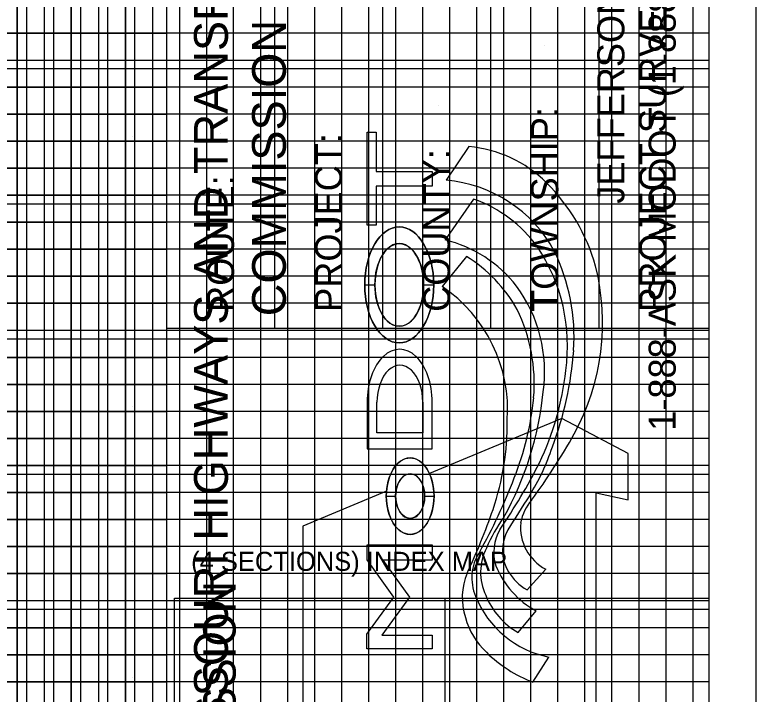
# Model space of a CAD drawing. Extents: x 90.2 to 116.7, y 59.2 to 76.5.
import ezdxf

# ---------------------------------------------------------------- set-up
doc = ezdxf.new("R2010")
doc.units = 0
for name, color, linetype in [('Border-Border', 7, 'Continuous'), ('Border-Bridge survey map and note', 7, 'Continuous'), ('Border-Cookie Cutter Template', 7, 'Continuous'), ('Border-English bridge partial major lines', 7, 'Continuous'), ('Border-English bridge partial minor lines', 7, 'Continuous'), ('Border-English bridge xsection major lines', 7, 'Continuous'), ('Border-English bridge xsection minor lines', 7, 'Continuous'), ('Border-English xsection major lines', 7, 'Continuous'), ('Border-English xsection minor lines', 7, 'Continuous'), ('Border-Full profile major grid lines', 7, 'Continuous'), ('Border-Geopak xsection major grid lines', 7, 'Continuous'), ('Border-Geopak xsection minor lines 1', 7, 'Continuous'), ('Border-Geopak xsection minor lines 2', 7, 'Continuous'), ('Border-Plan-profile major grid lines', 7, 'Continuous'), ('Border-Plotting block', 7, 'Continuous'), ('Border-Title block - A-size Landscape Electronic Seal', 7, 'Continuous'), ('Border-Title block - Final Plans Consultant Manual Seal', 7, 'Continuous'), ('Border-Title block - Final Plans Electronic Seal', 7, 'Continuous'), ('Border-Title block - Location Survey Electronic Seal', 7, 'Continuous'), ('Border-Xsection shape', 7, 'Continuous')]:
    doc.layers.add(name, color=color, linetype=linetype)

msp = doc.modelspace()

# ---------------------------------------------------------------- linework, layer by layer
at = {"layer": 'Border-Border'}
msp.add_line((116.4051, 76.3159), (116.4051, 59.3368), dxfattribs=at)
at = {"layer": 'Border-Bridge survey map and note'}
msp.add_line((115.5901, 64.3446), (115.5901, 62.6635), dxfattribs=at)
msp.add_lwpolyline([(114.7568, 62.6635), (114.7568, 64.3446), (116.4051, 64.3446)], dxfattribs=at)
at = {"layer": 'Border-Cookie Cutter Template'}
for p, q in [((114.7319, 76.3159), (114.7319, 59.3368)), ((116.4051, 76.3159), (116.4051, 59.3368))]:
    msp.add_line(p, q, dxfattribs=at)
at = {"layer": 'Border-English bridge partial major lines'}
for p, q in [((114.9385, 62.6701), (114.9385, 76.3159)), ((115.7718, 76.3159), (115.7718, 62.6701)), ((90.3636, 66.0034), (116.4051, 66.0034)), ((90.3636, 65.1701), (116.4051, 65.1701)), ((90.3636, 64.3368), (116.4051, 64.3368))]:
    msp.add_line(p, q, dxfattribs=at)
at = {"layer": 'Border-English bridge partial minor lines'}
for p, q in [((114.2718, 76.3159), (114.2718, 62.6701)), ((114.3551, 76.3159), (114.3551, 62.6701)), ((114.4385, 76.3159), (114.4385, 62.6701)), ((114.5218, 76.3159), (114.5218, 62.6701)), ((114.6051, 76.3159), (114.6051, 62.6701)), ((114.6885, 76.3159), (114.6885, 62.6701)), ((114.7718, 76.3159), (114.7718, 62.6701)), ((114.8551, 76.3159), (114.8551, 62.6701)), ((115.0218, 76.3159), (115.0218, 62.6701)), ((115.1051, 76.3159), (115.1051, 62.6701)), ((115.1885, 76.3159), (115.1885, 62.6701)), ((115.2718, 76.3159), (115.2718, 62.6701)), ((115.3551, 76.3159), (115.3551, 62.6701)), ((115.4385, 76.3159), (115.4385, 62.6701)), ((115.5218, 76.3159), (115.5218, 62.6701)), ((115.6051, 76.3159), (115.6051, 62.6701)), ((115.6885, 76.3159), (115.6885, 62.6701)), ((115.8551, 76.3159), (115.8551, 62.6701)), ((115.9385, 76.3159), (115.9385, 62.6701)), ((116.0218, 76.3159), (116.0218, 62.6701)), ((116.1051, 76.3159), (116.1051, 62.6701)), ((116.1885, 76.3159), (116.1885, 62.6701)), ((116.2718, 76.3159), (116.2718, 62.6701)), ((116.3551, 76.3159), (116.3551, 62.6701)), ((116.4051, 66.0867), (90.3636, 66.0867)), ((116.4051, 65.9201), (90.3636, 65.9201)), ((116.4051, 65.8367), (90.3636, 65.8367)), ((116.4051, 65.7534), (90.3636, 65.7534)), ((116.4051, 65.6701), (90.3636, 65.6701)), ((116.4051, 65.5867), (90.3636, 65.5867)), ((116.4051, 65.5034), (90.3636, 65.5034)), ((116.4051, 65.4201), (90.3636, 65.4201)), ((116.4051, 65.3367), (90.3636, 65.3367)), ((116.4051, 65.2534), (90.3636, 65.2534)), ((116.4051, 65.0867), (90.3636, 65.0867)), ((116.4051, 65.0034), (90.3636, 65.0034)), ((116.4051, 64.9201), (90.3636, 64.9201)), ((116.4051, 64.8367), (90.3636, 64.8367)), ((116.4051, 64.7534), (90.3636, 64.7534)), ((116.4051, 64.6701), (90.3636, 64.6701)), ((116.4051, 64.5867), (90.3636, 64.5867)), ((116.4051, 64.5034), (90.3636, 64.5034)), ((116.4051, 64.4201), (90.3636, 64.4201)), ((116.4051, 64.2534), (90.3636, 64.2534)), ((116.4051, 64.1701), (90.3636, 64.1701)), ((116.4051, 64.0868), (90.3636, 64.0868))]:
    msp.add_line(p, q, dxfattribs=at)
at = {"layer": 'Border-English bridge xsection major lines'}
for p, q in [((114.9385, 62.6635), (114.9385, 76.3159)), ((115.7718, 76.3159), (115.7718, 62.6635)), ((90.3636, 66.0034), (116.4051, 66.0034)), ((90.3636, 65.1701), (116.4051, 65.1701)), ((90.3636, 64.3368), (116.4051, 64.3368))]:
    msp.add_line(p, q, dxfattribs=at)
at = {"layer": 'Border-English bridge xsection minor lines'}
for p, q in [((114.2718, 76.3159), (114.2718, 62.6635)), ((114.3551, 76.3159), (114.3551, 62.6635)), ((114.4385, 76.3159), (114.4385, 62.6635)), ((114.5218, 76.3159), (114.5218, 62.6635)), ((114.6051, 76.3159), (114.6051, 62.6635)), ((114.6885, 76.3159), (114.6885, 62.6635)), ((114.7718, 76.3159), (114.7718, 62.6635)), ((114.8551, 76.3159), (114.8551, 62.6635)), ((115.0218, 76.3159), (115.0218, 62.6635)), ((115.1051, 76.3159), (115.1051, 62.6635)), ((115.1885, 76.3159), (115.1885, 62.6635)), ((115.2718, 76.3159), (115.2718, 62.6635)), ((115.3551, 76.3159), (115.3551, 62.6635)), ((115.4385, 76.3159), (115.4385, 62.6635)), ((115.5218, 76.3159), (115.5218, 62.6635)), ((115.6051, 76.3159), (115.6051, 62.6635)), ((115.6885, 76.3159), (115.6885, 62.6635)), ((115.8551, 76.3159), (115.8551, 62.6635)), ((115.9385, 76.3159), (115.9385, 62.6635)), ((116.0218, 76.3159), (116.0218, 62.6635)), ((116.1051, 76.3159), (116.1051, 62.6635)), ((116.1885, 76.3159), (116.1885, 62.6635)), ((116.2718, 76.3159), (116.2718, 62.6635)), ((116.3551, 76.3159), (116.3551, 62.6635)), ((116.4051, 66.0867), (90.3636, 66.0867)), ((116.4051, 65.9201), (90.3636, 65.9201)), ((116.4051, 65.8367), (90.3636, 65.8367)), ((116.4051, 65.7534), (90.3636, 65.7534)), ((116.4051, 65.6701), (90.3636, 65.6701)), ((116.4051, 65.5867), (90.3636, 65.5867)), ((116.4051, 65.5034), (90.3636, 65.5034)), ((116.4051, 65.4201), (90.3636, 65.4201)), ((116.4051, 65.3367), (90.3636, 65.3367)), ((116.4051, 65.2534), (90.3636, 65.2534)), ((116.4051, 65.0867), (90.3636, 65.0867)), ((116.4051, 65.0034), (90.3636, 65.0034)), ((116.4051, 64.9201), (90.3636, 64.9201)), ((116.4051, 64.8367), (90.3636, 64.8367)), ((116.4051, 64.7534), (90.3636, 64.7534)), ((116.4051, 64.6701), (90.3636, 64.6701)), ((116.4051, 64.5867), (90.3636, 64.5867)), ((116.4051, 64.5034), (90.3636, 64.5034)), ((116.4051, 64.4201), (90.3636, 64.4201)), ((116.4051, 64.2534), (90.3636, 64.2534)), ((116.4051, 64.1701), (90.3636, 64.1701)), ((116.4051, 64.0868), (90.3636, 64.0868))]:
    msp.add_line(p, q, dxfattribs=at)
at = {"layer": 'Border-English xsection major lines'}
for p, q in [((90.3636, 66.0034), (114.7319, 66.0034)), ((90.3636, 65.1701), (114.7319, 65.1701)), ((90.3636, 64.3368), (114.7319, 64.3368))]:
    msp.add_line(p, q, dxfattribs=at)
at = {"layer": 'Border-English xsection minor lines'}
for p, q in [((114.2718, 59.3368), (114.2718, 76.3159)), ((114.4385, 59.3368), (114.4385, 76.3159)), ((114.6051, 59.3368), (114.6051, 76.3159)), ((90.3636, 65.8367), (114.7319, 65.8367)), ((90.3636, 65.6701), (114.7319, 65.6701)), ((90.3636, 65.5034), (114.7319, 65.5034)), ((90.3636, 65.3367), (114.7319, 65.3367)), ((90.3636, 65.0034), (114.7319, 65.0034)), ((90.3636, 64.8367), (114.7319, 64.8367)), ((90.3636, 64.6701), (114.7319, 64.6701)), ((90.3636, 64.5034), (114.7319, 64.5034)), ((90.3636, 64.1701), (114.7319, 64.1701))]:
    msp.add_line(p, q, dxfattribs=at)
at = {"layer": 'Border-Full profile major grid lines'}
for p, q in [((114.732, 65.5868), (90.3636, 65.5868)), ((114.732, 64.7534), (90.3636, 64.7534))]:
    msp.add_line(p, q, dxfattribs=at)
at = {"layer": 'Border-Geopak xsection major grid lines'}
for p, q in [((90.3636, 66.0034), (114.7319, 66.0034)), ((90.3636, 65.1701), (114.7319, 65.1701)), ((90.3636, 64.3368), (114.7319, 64.3368))]:
    msp.add_line(p, q, dxfattribs=at)
at = {"layer": 'Border-Geopak xsection minor lines 1'}
for p, q in [((114.301, 59.3368), (114.301, 76.3159)), ((114.4676, 59.3368), (114.4676, 76.3159)), ((114.6343, 59.3368), (114.6343, 76.3159)), ((90.3636, 66.0867), (114.7319, 66.0867)), ((90.3636, 65.9201), (114.7319, 65.9201)), ((90.3636, 65.7534), (114.7319, 65.7534)), ((90.3636, 65.5867), (114.7319, 65.5867)), ((90.3636, 65.4201), (114.7319, 65.4201)), ((90.3636, 65.2534), (114.7319, 65.2534)), ((90.3636, 65.0867), (114.7319, 65.0867)), ((90.3636, 64.9201), (114.7319, 64.9201)), ((90.3636, 64.7534), (114.7319, 64.7534)), ((90.3636, 64.5867), (114.7319, 64.5867)), ((90.3636, 64.4201), (114.7319, 64.4201)), ((90.3636, 64.2534), (114.7319, 64.2534)), ((90.3636, 64.0868), (114.7319, 64.0868))]:
    msp.add_line(p, q, dxfattribs=at)
at = {"layer": 'Border-Geopak xsection minor lines 2'}
for p, q in [((114.3843, 59.3368), (114.3843, 76.3159)), ((114.551, 59.3368), (114.551, 76.3159)), ((90.3636, 65.8367), (114.7319, 65.8367)), ((90.3636, 65.6701), (114.7319, 65.6701)), ((90.3636, 65.5034), (114.7319, 65.5034)), ((90.3636, 65.3367), (114.7319, 65.3367)), ((90.3636, 65.0034), (114.7319, 65.0034)), ((90.3636, 64.8367), (114.7319, 64.8367)), ((90.3636, 64.6701), (114.7319, 64.6701)), ((90.3636, 64.5034), (114.7319, 64.5034)), ((90.3636, 64.1701), (114.7319, 64.1701))]:
    msp.add_line(p, q, dxfattribs=at)
at = {"layer": 'Border-Plan-profile major grid lines'}
for p, q in [((114.732, 65.5868), (90.3636, 65.5868)), ((114.732, 64.7534), (90.3636, 64.7534))]:
    msp.add_line(p, q, dxfattribs=at)
at = {"layer": 'Border-Plotting block'}
msp.add_lwpolyline([(90.2177, 59.1597), (116.551, 59.1597), (116.551, 76.493), (90.2177, 76.493)], close=True, dxfattribs=at)
at = {"layer": 'Border-Title block - A-size Landscape Electronic Seal'}
for p, q in [((116.4051, 65.976), (111.7415, 65.976)), ((114.6273, 65.7677), (114.6273, 65.7677)), ((116.4051, 65.5593), (111.7415, 65.5593)), ((114.6273, 65.351), (114.6273, 65.351)), ((116.4051, 65.1427), (111.7415, 65.1427)), ((114.6273, 64.9344), (114.6273, 64.9344)), ((116.4051, 64.726), (111.7415, 64.726)), ((114.6273, 64.5177), (114.6273, 64.5177)), ((116.4051, 64.3093), (111.7415, 64.3093)), ((114.6273, 64.101), (114.6273, 64.101))]:
    msp.add_line(p, q, dxfattribs=at)
at = {"layer": 'Border-Title block - Final Plans Consultant Manual Seal'}
for p, q in [((114.7319, 76.3159), (114.7319, 59.3368)), ((115.6648, 65.7365), (115.5943, 65.633)), ((115.6794, 65.5746), (115.5913, 65.4487)), ((115.657, 65.3979), (115.5825, 65.3053)), ((115.351, 64.9483), (115.351, 64.8047)), ((115.3812, 64.8542), (115.3812, 64.9483)), ((115.5228, 64.9483), (115.5228, 64.8542)), ((115.5517, 64.8047), (115.5517, 64.9483)), ((115.9513, 64.8987), (115.5429, 64.7289)), ((116.1566, 64.7902), (115.9513, 64.8987)), ((115.5228, 64.8542), (115.3812, 64.8542)), ((115.351, 64.8047), (115.5517, 64.8047)), ((116.1566, 64.6476), (116.1566, 64.7902)), ((115.4106, 64.6738), (115.1527, 64.5666)), ((116.0569, 63.9757), (116.0569, 64.6687)), ((116.0569, 64.6687), (116.1566, 64.6476)), ((115.1527, 64.5666), (115.1527, 63.8346)), ((115.8441, 64.3701), (115.9018, 64.4334)), ((115.8167, 64.2382), (115.8725, 64.3054)), ((115.8618, 64.0858), (115.9118, 64.163))]:
    msp.add_line(p, q, dxfattribs=at)
for points in [[(115.3509, 65.4943), (115.3509, 65.7813), (115.3789, 65.7813), (115.3789, 65.6601), (115.5517, 65.6601), (115.5517, 65.6146), (115.3789, 65.6146), (115.3789, 65.4943)], [(115.5517, 64.1877), (115.3503, 64.1877), (115.3503, 64.2332), (115.4334, 64.3472), (115.351, 64.4629), (115.351, 64.5091), (115.5517, 64.5091), (115.5517, 64.4613), (115.3998, 64.4613), (115.4813, 64.3472), (115.3966, 64.23), (115.5517, 64.23)]]:
    msp.add_lwpolyline(points, close=True, dxfattribs=at)
for centre, radius, start, end in [((115.6303, 65.3501), 0.388, 45.1693, 84.902), ((115.5574, 65.2123), 0.4224, 28.5725, 84.9889), ((115.492, 65.2086), 0.5858, 15.8221, 45.3322), ((115.5466, 65.192), 0.405, 35.4806, 70.8474), ((115.4978, 65.0624), 0.3975, 37.8205, 76.3964), ((115.4228, 65.1228), 0.5461, 351.9272, 33.854), ((115.3775, 65.148), 0.6118, 356.2526, 25.8037), ((115.4216, 65.015), 0.4494, 29.2666, 58.4191), ((115.3598, 65.1938), 0.7174, 331.4589, 14.0852), ((115.3224, 64.9235), 0.462, 55.7274, 55.7276), ((115.3224, 64.9235), 0.462, 356.1033, 55.7272), ((115.4555, 65.0429), 0.4429, 351.8718, 36.464), ((115.3442, 65.006), 0.5222, 355.2048, 25.9837), ((114.9337, 65.1846), 1.0571, 339.2778, 355.8465), ((115.0952, 65.1401), 0.8734, 334.3097, 353.8237), ((114.9042, 65.0789), 0.9947, 330.8019, 354.3058), ((114.9626, 65.0497), 0.9063, 338.3366, 354.4662), ((114.937, 64.8871), 0.8463, 341.469, 0.3416), ((114.3916, 65.7416), 1.8298, 323.2547, 330.8755), ((115.2318, 65.0425), 0.7285, 328.3334, 341.428), ((114.3252, 65.55), 1.7454, 325.3377, 333.1413), ((114.1314, 65.3593), 1.7931, 330.8271, 338.9455), ((118.116, 63.1564), 2.718, 146.4094, 149.0393), ((115.9779, 64.5468), 0.1564, 140.188, 168.8506), ((114.045, 65.1961), 1.7902, 334.3727, 341.1665), ((116.1615, 64.3098), 0.4815, 143.8762, 156.8714), ((115.8806, 64.4865), 0.1392, 149.4043, 197.7638), ((115.9714, 64.5635), 0.1475, 174.7527, 241.8661), ((115.8957, 64.4915), 0.1272, 150.2552, 210.6413), ((115.8672, 64.4241), 0.1663, 153.2735, 205.15), ((115.8179, 64.4069), 0.1441, 147.0199, 203.0239), ((116.0026, 64.5472), 0.2746, 202.0629, 241.7201), ((115.8421, 64.3468), 0.1977, 157.7092, 198.1728), ((115.9279, 64.5134), 0.166, 211.4954, 239.6897), ((115.9703, 64.4641), 0.3068, 201.7288, 258.9961), ((115.9325, 64.4398), 0.2325, 201.8104, 240.1114), ((115.8742, 64.3442), 0.2278, 195.0361, 226.9912), ((116.0103, 64.4742), 0.4158, 225.4988, 249.0787)]:
    msp.add_arc(centre, radius, start, end, dxfattribs=at)
for centre, major_axis, ratio in [((115.45, 65.3101), (0, 0.1787), 0.595517), ((115.45, 65.31), (0, -0.1275), 0.589579), ((115.4836, 64.659), (0, 0.118), 0.623747), ((115.4836, 64.659), (0, 0.0686), 0.65252)]:
    msp.add_ellipse(centre, major_axis=major_axis, ratio=ratio, dxfattribs=at)
for centre, major_axis, ratio in [((115.4513, 64.9483), (0, -0.1634), 0.614143), ((115.452, 64.9483), (0, -0.114), 0.62091)]:
    msp.add_ellipse(centre, major_axis=major_axis, ratio=ratio, start_param=1.570796, end_param=4.712389, dxfattribs=at)
at = {"layer": 'Border-Title block - Final Plans Electronic Seal'}
for p, q in [((114.7319, 76.3159), (114.7319, 59.3368)), ((115.6648, 65.7365), (115.5943, 65.633)), ((115.6794, 65.5746), (115.5913, 65.4487)), ((115.657, 65.3979), (115.5825, 65.3053)), ((115.3436, 65.31), (115.3749, 65.31)), ((115.3436, 65.31), (115.3749, 65.31)), ((115.5252, 65.31), (115.5564, 65.31)), ((115.5252, 65.31), (115.5564, 65.31)), ((115.351, 64.9483), (115.351, 64.8047)), ((115.3812, 64.8542), (115.3812, 64.9483)), ((115.5228, 64.9483), (115.5228, 64.8542)), ((115.5517, 64.8047), (115.5517, 64.9483)), ((115.9513, 64.8987), (115.5429, 64.7289)), ((116.1566, 64.7902), (115.9513, 64.8987)), ((115.5228, 64.8542), (115.3812, 64.8542)), ((115.351, 64.8047), (115.5517, 64.8047)), ((116.1566, 64.6476), (116.1566, 64.7902)), ((115.4106, 64.6738), (115.1527, 64.5666)), ((115.41, 64.659), (115.4393, 64.659)), ((115.41, 64.659), (115.4393, 64.659)), ((115.4393, 64.659), (115.4388, 64.659)), ((115.4393, 64.659), (115.4388, 64.659)), ((115.5284, 64.659), (115.5572, 64.659)), ((115.5284, 64.659), (115.5572, 64.659)), ((116.0569, 63.9757), (116.0569, 64.6687)), ((116.0569, 64.6687), (116.1566, 64.6476)), ((115.1527, 64.5666), (115.1527, 63.8346)), ((115.8441, 64.3701), (115.9018, 64.4334)), ((115.8167, 64.2382), (115.8725, 64.3054)), ((115.8618, 64.0858), (115.9118, 64.163))]:
    msp.add_line(p, q, dxfattribs=at)
for points in [[(115.3509, 65.4943), (115.3509, 65.7813), (115.3789, 65.7813), (115.3789, 65.6601), (115.5517, 65.6601), (115.5517, 65.6146), (115.3789, 65.6146), (115.3789, 65.4943)], [(115.5517, 64.1877), (115.3503, 64.1877), (115.3503, 64.2332), (115.4334, 64.3472), (115.351, 64.4629), (115.351, 64.5091), (115.5517, 64.5091), (115.5517, 64.4613), (115.3998, 64.4613), (115.4813, 64.3472), (115.3966, 64.23), (115.5517, 64.23)]]:
    msp.add_lwpolyline(points, close=True, dxfattribs=at)
for centre, radius, start, end in [((115.6303, 65.3501), 0.388, 45.1693, 84.902), ((115.5574, 65.2123), 0.4224, 28.5725, 84.9889), ((115.492, 65.2086), 0.5858, 15.8221, 45.3322), ((115.5466, 65.192), 0.405, 35.4806, 70.8474), ((115.4978, 65.0624), 0.3975, 37.8205, 76.3964), ((115.4228, 65.1228), 0.5461, 351.9272, 33.854), ((115.3775, 65.148), 0.6118, 356.2526, 25.8037), ((115.4216, 65.015), 0.4494, 29.2666, 58.4191), ((115.3598, 65.1938), 0.7174, 331.4589, 14.0852), ((115.3224, 64.9235), 0.462, 55.7274, 55.7276), ((115.3224, 64.9235), 0.462, 356.1033, 55.7272), ((115.4555, 65.0429), 0.4429, 351.8718, 36.464), ((115.3442, 65.006), 0.5222, 355.2048, 25.9837), ((114.9337, 65.1846), 1.0571, 339.2778, 355.8465), ((115.0952, 65.1401), 0.8734, 334.3097, 353.8237), ((114.9042, 65.0789), 0.9947, 330.8019, 354.3058), ((114.9626, 65.0497), 0.9063, 338.3366, 354.4662), ((114.937, 64.8871), 0.8463, 341.469, 0.3416), ((114.3916, 65.7416), 1.8298, 323.2547, 330.8755), ((115.2318, 65.0425), 0.7285, 328.3334, 341.428), ((114.3252, 65.55), 1.7454, 325.3377, 333.1413), ((114.1314, 65.3593), 1.7931, 330.8271, 338.9455), ((118.116, 63.1564), 2.718, 146.4094, 149.0393), ((115.9779, 64.5468), 0.1564, 140.188, 168.8506), ((114.045, 65.1961), 1.7902, 334.3727, 341.1665), ((116.1615, 64.3098), 0.4815, 143.8762, 156.8714), ((115.8806, 64.4865), 0.1392, 149.4043, 197.7638), ((115.9714, 64.5635), 0.1475, 174.7527, 241.8661), ((115.8957, 64.4915), 0.1272, 150.2552, 210.6413), ((115.8672, 64.4241), 0.1663, 153.2735, 205.15), ((115.8179, 64.4069), 0.1441, 147.0199, 203.0239), ((116.0026, 64.5472), 0.2746, 202.0629, 241.7201), ((115.8421, 64.3468), 0.1977, 157.7092, 198.1728), ((115.9279, 64.5134), 0.166, 211.4954, 239.6897), ((115.9703, 64.4641), 0.3068, 201.7288, 258.9961), ((115.9325, 64.4398), 0.2325, 201.8104, 240.1114), ((115.8742, 64.3442), 0.2278, 195.0361, 226.9912), ((116.0103, 64.4742), 0.4158, 225.4988, 249.0787)]:
    msp.add_arc(centre, radius, start, end, dxfattribs=at)
for centre, major_axis, ratio, start_param, end_param in [((115.45, 65.31), (0, -0.1787), 0.595517, 1.571051, 4.712134), ((115.45, 65.31), (0, -0.1275), 0.589579, 1.570796, 4.712389), ((115.45, 65.3101), (0, 0.1787), 0.595517, 1.571051, 4.712134), ((115.45, 65.31), (0, -0.1275), 0.589579, 4.712389, 7.853982), ((115.4513, 64.9483), (0, -0.1634), 0.614143, 1.570796, 4.712389), ((115.452, 64.9483), (0, -0.114), 0.62091, 1.570796, 4.712389), ((115.4836, 64.659), (0, -0.118), 0.623747, 1.570796, 4.712389), ((115.4836, 64.659), (0, -0.0686), 0.65252, 1.570796, 4.712389), ((115.4836, 64.659), (0, 0.118), 0.623747, 1.570796, 4.712389), ((115.4836, 64.659), (0, 0.0686), 0.65252, 1.570796, 4.712389)]:
    msp.add_ellipse(centre, major_axis=major_axis, ratio=ratio, start_param=start_param, end_param=end_param, dxfattribs=at)
at = {"layer": 'Border-Title block - Location Survey Electronic Seal'}
for p, q in [((114.7319, 76.3159), (114.7319, 59.3368)), ((115.0653, 70.1765), (115.0653, 65.1765)), ((115.3986, 70.1765), (115.3986, 65.1765)), ((115.7319, 70.1765), (115.7319, 65.1765)), ((116.0653, 70.1765), (116.0653, 65.1765)), ((115.8986, 66.047), (115.8986, 66.047)), ((115.8986, 66.047), (115.8986, 66.047)), ((115.2319, 65.9222), (115.2319, 65.9222)), ((115.5701, 65.8635), (115.5701, 65.8635)), ((114.8986, 65.7773), (114.8986, 65.7773)), ((114.7319, 65.1765), (116.4051, 65.1765))]:
    msp.add_line(p, q, dxfattribs=at)
at = {"layer": 'Border-Xsection shape'}
msp.add_lwpolyline([(114.7319, 59.3368), (90.3636, 59.3368), (90.3636, 76.3159), (114.7319, 76.3159)], close=True, dxfattribs=at)

# ---------------------------------------------------------------- texts
at = {"layer": 'Border-Bridge survey map and note'}
msp.add_text('(4 SECTIONS) INDEX MAP', height=0.058803, dxfattribs=at).set_placement((114.808, 64.4286))
at = {"layer": 'Border-Title block - Final Plans Consultant Manual Seal'}
for s, height, p in [('JEFFERSON CITY, MO 65102', 0.083333, (116.1444, 65.5604)), ('MISSOURI HIGHWAYS AND TRANSPORTATION', 0.104166, (114.9212, 63.7944)), ('1-888-ASK-MODOT (1-888-275-6636)', 0.083333, (116.3027, 64.8607)), ('COMMISSION', 0.10417, (115.1003, 65.2136))]:
    msp.add_text(s, height=height, rotation=90, dxfattribs=at).set_placement(p)
at = {"layer": 'Border-Title block - Final Plans Electronic Seal'}
for s, height, p in [('JEFFERSON CITY, MO 65102', 0.083333, (116.1444, 65.5604)), ('MISSOURI HIGHWAYS AND TRANSPORTATION', 0.104166, (114.9212, 63.7944)), ('1-888-ASK-MODOT (1-888-275-6636)', 0.083333, (116.3027, 64.8607)), ('COMMISSION', 0.10417, (115.1003, 65.2136))]:
    msp.add_text(s, height=height, rotation=90, dxfattribs=at).set_placement(p)
at = {"layer": 'Border-Title block - Location Survey Electronic Seal'}
for s, height, p in [('PROJECT SURVEYOR:', 0.083333, (116.2736, 65.2271)), ('TOWNSHIP:', 0.08333, (115.9403, 65.2271)), ('PROJECT:', 0.08333, (115.2736, 65.2271)), ('COUNTY:', 0.08333, (115.6069, 65.2271)), ('ROUTE:', 0.08333, (114.9403, 65.2271)), ('SURVEY FOR: MISSOURI HIGHWAYS AND TRANSPORTATION COMMISSION', 0.1, (114.9455, 59.5227))]:
    msp.add_text(s, height=height, rotation=90, dxfattribs=at).set_placement(p)

doc.saveas('drawing.dxf')
